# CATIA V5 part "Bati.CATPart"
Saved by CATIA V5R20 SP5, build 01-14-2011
Part number: Bati
Bounding box of the stored display mesh (mm): x -20 to 80, y -270 to -30, z -70 to 70
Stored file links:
  U:\CFAO\Thinkmotion\Bati.CATPart
  U:\CFAO\Thinkmotion\Bras Articule.CATProduct
  U:\CFAO\Thinkmotion\Squelette Bati.CATPart
  U:\CFAO\Thinkmotion\Squelette Corps verin 1.CATPart
  J:\Projet Thinkmotion\areckea\Squelette Tige verin 1.CATPart
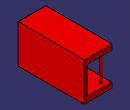
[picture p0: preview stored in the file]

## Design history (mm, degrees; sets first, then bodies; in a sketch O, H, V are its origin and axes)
Set1
  Plane1: linked copy from another document
  Point1 to Point3: linked copy from another document
  Plane2: linked copy from another document
Body1 (main body)
  Sketch1 on Plane1, origin (0, 0, 0), H (1, 0, 0), V (0, 1, 0)
    circle A1 centre (0, -50) radius 5
    point P1 (0, -50)
    circle A2 centre (0, -150) radius 5
    point P2 (0, -150)
    circle A3 centre (0, -250) radius 5
    point P3 (0, -250)
    reference projected point E1 (0, -250) from Point1
    reference projected point E2 (0, -150) from Point2
    reference projected point E3 (0, -50) from Point3
    radius A3 = 5
    radius A2 = 5
    radius A1 = 5
    coincidence: P1 V, P2 V, P3 V
    concentricity: A3 E1, A2 E2, A1 E3
  Pad1: profile Sketch1, direction (0, 0, 1), length 50, mirrored extent
  Sketch2 on Plane2, origin (0, -150, 0), H (-1, 0, 0), V (0, 0, 1)
    line L1 (-70, 50) -> (20, 50)
    line L2 (20, 50) -> (20, 70)
    line L3 (20, 70) -> (-80, 70)
    line L4 (-80, 70) -> (-80, -70)
    line L5 (-80, -70) -> (20, -70)
    point P6 (20, -70)
    line L6 (20, -70) -> (20, -50)
    line L7 (20, -50) -> (-70, -50)
    line L8 (-70, -50) -> (-70, 50)
    reference projected point E1 (0, 0) from Point3
    reference projected point E2 (0, 0) from Point3
    length L2 = 20
    length L6 = 20
    distance L4 L8 = 10
    length L3 = 100
    distance L8 E1 = 70
    distance E2 L1 = 50
    horizontal: L1 H, L3 H, L5 H, L7 H
    vertical: L2 V, L4 V, L6 V, L8 V
    coincidence: P6 L2
    symmetry: L1 L7 H
  Pad2: profile Sketch2, direction (0, 1, 0), length 120, mirrored extent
